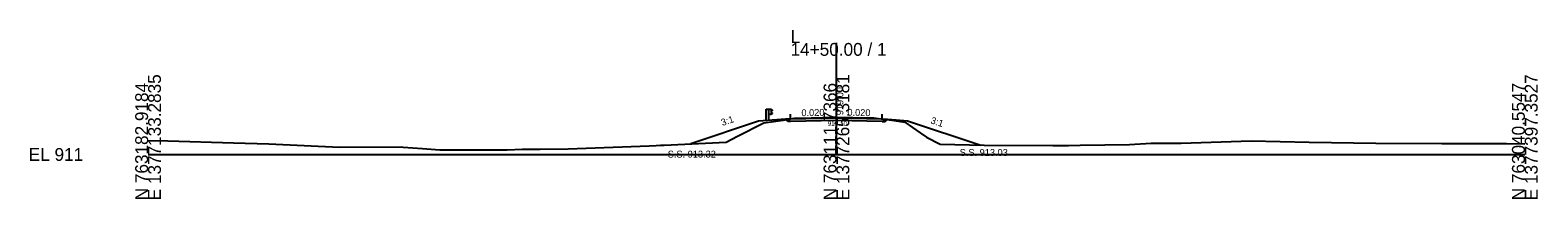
# Model space of a CAD drawing. Extents: x -26 to 303, y -10 to 6523.
# Drawn here: x -25.7 to 302.8, y 4490.3 to 4527.1 of the extents above; entities that cross this region are included whole.
import ezdxf

# ---------------------------------------------------------------- set-up
doc = ezdxf.new("R2010")
doc.units = 0
for name, color, linetype in [('Exist Cross Section Cell', 7, 'Continuous'), ('Exist XS Center Line Elevation Label', 7, 'Continuous'), ('Exist XS Ground Line', 7, 'Continuous'), ('Prop XS Dump Level', 7, 'Continuous'), ('Prop XS Elevation Labels', 7, 'Continuous'), ('Prop XS EOT Tick Mark', 7, 'Continuous'), ('Prop XS Finish Grade', 7, 'Continuous'), ('Prop XS Finish Grade Earthwork', 7, 'Continuous'), ('Prop XS Finish Grade Pavement', 7, 'Continuous'), ('Prop XS Guardrail', 7, 'Continuous'), ('Prop XS Pvmt Edge Slope', 7, 'Continuous'), ('Prop XS SE Text', 7, 'Continuous'), ('Prop XS Side Slope Text', 7, 'Continuous'), ('Prop XS SS Elevation Text', 7, 'Continuous'), ('Prop XS Subgrade Earthwork', 7, 'Continuous')]:
    doc.layers.add(name, color=color, linetype=linetype)

msp = doc.modelspace()

# ---------------------------------------------------------------- linework, layer by layer
at = {"layer": 'Exist Cross Section Cell'}
for p, q in [((150, 4500), (150, 4524.32)), ((0, 4500), (150, 4500)), ((150, 4500), (300, 4500))]:
    msp.add_line(p, q, dxfattribs=at)
at = {"layer": 'Exist XS Ground Line'}
for p, q in [((134.16, 4506.93), (138.39, 4507.51)), ((138.39, 4507.51), (140.85, 4507.9)), ((140.85, 4507.9), (141.92, 4507.92)), ((141.92, 4507.92), (149.56, 4508.11)), ((149.56, 4508.11), (150, 4508.1)), ((150, 4508.1), (157.1, 4507.98)), ((157.1, 4507.98), (158.14, 4507.97)), ((158.14, 4507.97), (159.14, 4507.84)), ((159.14, 4507.84), (162.1, 4507.45)), ((128.44, 4503.99), (134.16, 4506.93)), ((162.1, 4507.45), (164.87, 4507.05)), ((164.87, 4507.05), (168.27, 4504.7)), ((168.27, 4504.7), (169.66, 4503.8)), ((0, 4503.07), (4.29, 4502.95)), ((4.29, 4502.95), (18.6, 4502.54)), ((18.6, 4502.54), (26.29, 4502.33)), ((26.29, 4502.33), (41.73, 4501.6)), ((41.73, 4501.6), (55.14, 4501.63)), ((55.14, 4501.63), (55.6, 4501.6)), ((55.6, 4501.6), (59.82, 4501.29)), ((59.82, 4501.29), (63.56, 4501.01)), ((63.56, 4501.01), (68.99, 4501.01)), ((68.99, 4501.01), (72.26, 4501.01)), ((72.26, 4501.01), (73.98, 4501.01)), ((73.98, 4501.01), (76.96, 4501.01)), ((76.96, 4501.01), (78.24, 4501.01)), ((78.24, 4501.01), (81.5, 4501.12)), ((81.5, 4501.12), (85.43, 4501.12)), ((85.43, 4501.12), (91.51, 4501.2)), ((91.51, 4501.2), (109.21, 4501.9)), ((109.21, 4501.9), (110.75, 4501.94)), ((110.75, 4501.94), (111.63, 4502)), ((111.63, 4502), (112.49, 4502.04)), ((112.49, 4502.04), (125.97, 4502.69)), ((125.97, 4502.69), (128.44, 4503.99)), ((169.66, 4503.8), (172.57, 4502.22)), ((172.57, 4502.22), (182.19, 4502.01)), ((182.19, 4502.01), (197.13, 4501.94)), ((197.13, 4501.94), (200.55, 4501.96)), ((200.55, 4501.96), (203.11, 4502.06)), ((203.11, 4502.06), (213.83, 4502.16)), ((213.83, 4502.16), (218.6, 4502.43)), ((218.6, 4502.43), (225.11, 4502.49)), ((225.11, 4502.49), (240.39, 4502.99)), ((240.39, 4502.99), (253.01, 4502.69)), ((253.01, 4502.69), (267.56, 4502.47)), ((267.56, 4502.47), (281.91, 4502.37)), ((281.91, 4502.37), (295.98, 4502.41)), ((295.98, 4502.41), (300, 4502.35))]:
    msp.add_line(p, q, dxfattribs=at)
at = {"layer": 'Prop XS Dump Level'}
for p, q in [((140, 4507.8), (150, 4508)), ((150, 4508), (160, 4507.8))]:
    msp.add_line(p, q, dxfattribs=at)
at = {"layer": 'Prop XS EOT Tick Mark'}
for p, q in [((140, 4507.8), (140, 4508.8)), ((160, 4507.8), (160, 4508.8))]:
    msp.add_line(p, q, dxfattribs=at)
at = {"layer": 'Prop XS Finish Grade'}
for p, q in [((140, 4507.8), (138.9, 4507.71)), ((160, 4507.8), (161.1, 4507.71))]:
    msp.add_line(p, q, dxfattribs=at)
at = {"layer": 'Prop XS Finish Grade Earthwork'}
for p, q in [((137, 4507.56), (133, 4507.24)), ((138.9, 4507.71), (137, 4507.56)), ((161.1, 4507.71), (163, 4507.56)), ((163, 4507.56), (165.5, 4507.36)), ((133, 4507.24), (118.26, 4502.32)), ((165.5, 4507.36), (181.49, 4502.03))]:
    msp.add_line(p, q, dxfattribs=at)
at = {"layer": 'Prop XS Finish Grade Pavement'}
for p, q in [((140, 4507.8), (150, 4508)), ((150, 4508), (160, 4507.8))]:
    msp.add_line(p, q, dxfattribs=at)
at = {"layer": 'Prop XS Guardrail'}
for p, q in [((134.68, 4509.87), (135.18, 4509.87)), ((134.68, 4507.37), (134.68, 4509.87)), ((135.18, 4509.87), (135.68, 4509.87)), ((135.18, 4509.87), (135.18, 4507.37)), ((135.68, 4508.74), (135.18, 4508.74)), ((135.68, 4509.87), (135.97, 4509.67)), ((135.97, 4509.55), (135.68, 4509.35)), ((135.68, 4509.35), (135.68, 4509.26)), ((135.68, 4509.26), (135.97, 4509.06)), ((135.97, 4508.94), (135.68, 4508.74)), ((135.97, 4509.67), (136, 4509.61)), ((136, 4509.61), (135.97, 4509.55)), ((135.97, 4509.06), (136, 4509)), ((136, 4509), (135.97, 4508.94))]:
    msp.add_line(p, q, dxfattribs=at)
at = {"layer": 'Prop XS Pvmt Edge Slope'}
for p, q in [((140, 4507.8), (139.4, 4507.2)), ((160, 4507.8), (160.6, 4507.2))]:
    msp.add_line(p, q, dxfattribs=at)
at = {"layer": 'Prop XS Subgrade Earthwork'}
for p, q in [((139.4, 4507.2), (138.9, 4507.71)), ((160.6, 4507.2), (161.1, 4507.71)), ((140, 4507.21), (139.4, 4507.2)), ((150, 4507.41), (140, 4507.21)), ((160, 4507.21), (150, 4507.41)), ((160, 4507.21), (160.6, 4507.2))]:
    msp.add_line(p, q, dxfattribs=at)

# ---------------------------------------------------------------- texts
at = {"layer": 'Exist Cross Section Cell'}
for s, p in [('14+50.00 / 1', (140, 4521.52)), ('L', (140, 4524.32)), ('EL 911', (-26, 4498.6))]:
    msp.add_text(s, height=2.8, dxfattribs=at).set_placement(p)
for s, p in [('E 1377133.2835', (2.8, 4490)), ('N 763182.9184', (0, 4490)), ('N 763111.7366', (150, 4490)), ('E 1377265.3181', (152.8, 4490)), ('N 763040.5547', (300, 4490)), ('E 1377397.3527', (302.8, 4490))]:
    msp.add_text(s, height=2.8, rotation=90, dxfattribs=at).set_placement(p)
at = {"layer": 'Exist XS Center Line Elevation Label'}
msp.add_text('919.10', height=0.998, dxfattribs=at).set_placement((148.1, 4506.23))
at = {"layer": 'Prop XS Dump Level'}
for p in [(137, 4507.52), (163, 4507.52), (163, 4507.52)]:
    msp.add_text('Case1', height=0.04, dxfattribs=at).set_placement(p)
at = {"layer": 'Prop XS Elevation Labels'}
msp.add_text(' 919.00', height=1.5, rotation=90, dxfattribs=at).set_placement((151.5, 4508))
at = {"layer": 'Prop XS SE Text'}
for rotation, p in [(1.1458, (142.38, 4508.34)), (358.8542, (152.38, 4508.45))]:
    msp.add_text('0.020', height=1.5, rotation=rotation, dxfattribs=at).set_placement(p)
at = {"layer": 'Prop XS Side Slope Text'}
for rotation, p in [(18.4349, (125.15, 4506.2)), (341.5651, (170.4, 4506.82))]:
    msp.add_text('3:1', height=1.5, rotation=rotation, dxfattribs=at).set_placement(p)
at = {"layer": 'Prop XS SS Elevation Text'}
for s, p in [('S.S. 913.03', (176.86, 4499.68)), ('S.S. 913.32', (113.24, 4499.32))]:
    msp.add_text(s, height=1.5, dxfattribs=at).set_placement(p)

doc.saveas('drawing.dxf')
